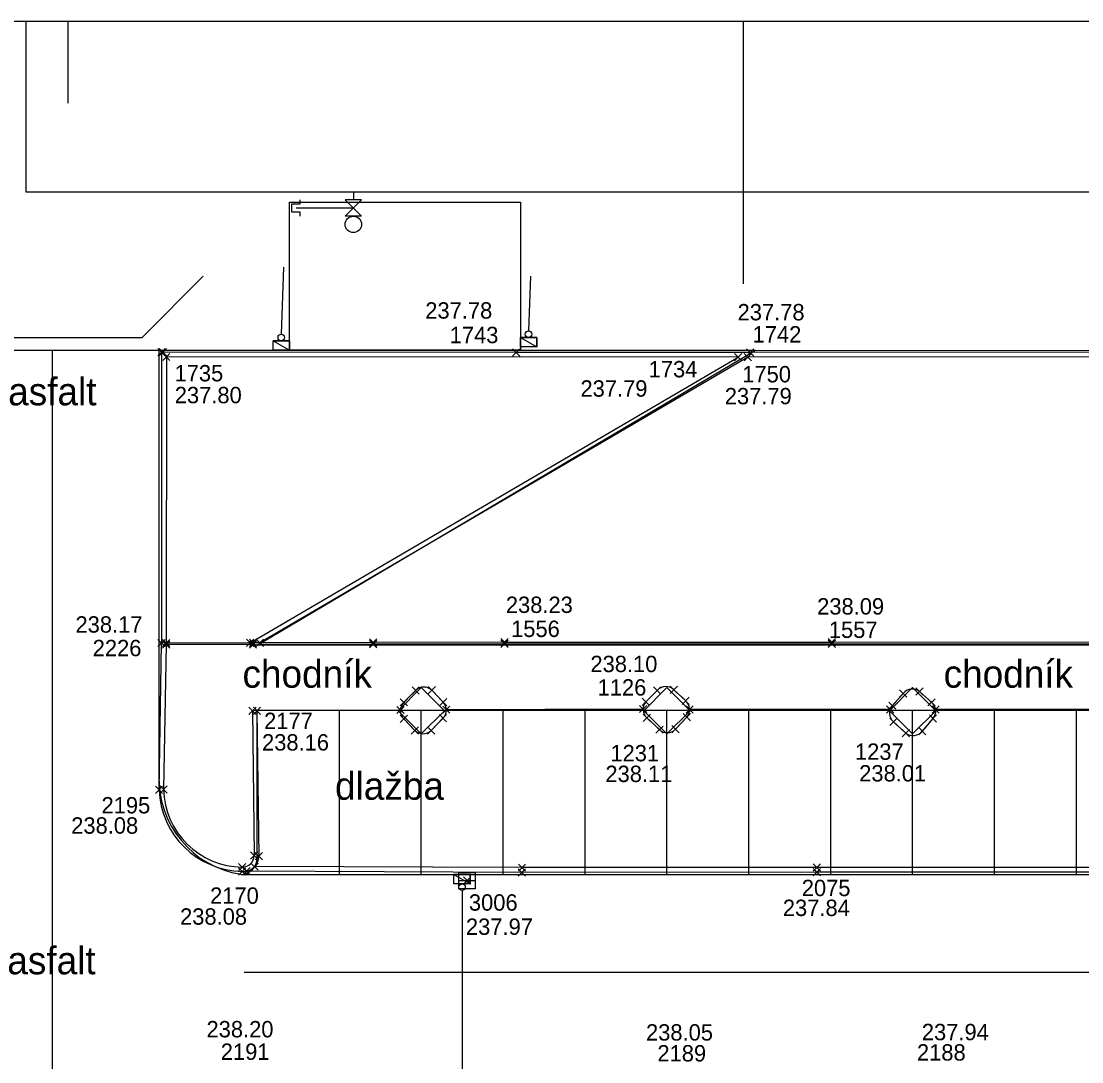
# Model space of a CAD drawing. Extents: x -264165 to -263733, y -1242319 to -1242245.
# Drawn here: x -263924.28 to -263891.9, y -1242276.71 to -1242244.94 of the extents above; entities that cross this region are included whole.
import ezdxf

# ---------------------------------------------------------------- set-up
doc = ezdxf.new("R2010")
doc.units = 0
for name, color, linetype in [('KFA_BOD_CISLO', 7, 'Continuous'), ('KFA_BOD_SYMBOL', 7, 'Continuous'), ('KFA_BOD_VYSKA', 7, 'Continuous'), ('KFA_SO_20-2_OBRUBNIKY_DOLNA_HRANA', 7, 'Continuous'), ('KFA_SO_20-2_OBRUBNIKY_HORNA_HRANA', 7, 'Continuous'), ('KFA_UV_BOD_CISLO', 7, 'Continuous'), ('KFA_UV_BOD_SYMBOL', 7, 'Continuous'), ('KFA_UV_BOD_VYSKA', 7, 'Continuous'), ('POPIS', 7, 'Continuous'), ('PROJEKT_OBRUBNIKY_KOMUNIKACIE', 7, 'Continuous'), ('PROJEKT_TDZ_VODOROVNE', 7, 'Continuous'), ('RAM_NA_TLAC_1-250', 7, 'Continuous'), ('SITUACIA_DSP_2D', 7, 'Continuous'), ('ULICNA_VPUST_POKLOP', 7, 'Continuous')]:
    doc.layers.add(name, color=color, linetype=linetype)

msp = doc.modelspace()

# ---------------------------------------------------------------- linework, layer by layer
at = {"layer": 'KFA_BOD_SYMBOL'}
for p, q in [((-263920.112, -1242255.15), (-263919.891, -1242254.93)), ((-263919.891, -1242255.15), (-263920.112, -1242254.93)), ((-263920.112, -1242255.15), (-263919.891, -1242254.93)), ((-263919.891, -1242255.15), (-263920.112, -1242254.93)), ((-263920.067, -1242255.15), (-263919.845, -1242254.93)), ((-263919.845, -1242255.15), (-263920.067, -1242254.93)), ((-263909.285, -1242255.159), (-263909.064, -1242254.938)), ((-263909.064, -1242255.159), (-263909.285, -1242254.938)), ((-263902.139, -1242255.157), (-263901.918, -1242254.937)), ((-263901.918, -1242255.157), (-263902.139, -1242254.937)), ((-263919.963, -1242255.298), (-263919.742, -1242255.076)), ((-263919.742, -1242255.298), (-263919.963, -1242255.076)), ((-263902.502, -1242255.303), (-263902.28, -1242255.083)), ((-263902.28, -1242255.303), (-263902.502, -1242255.083)), ((-263902.208, -1242255.302), (-263901.986, -1242255.08)), ((-263901.986, -1242255.302), (-263902.208, -1242255.08)), ((-263913.649, -1242264.015), (-263913.427, -1242263.795)), ((-263913.427, -1242264.015), (-263913.649, -1242263.795)), ((-263909.638, -1242264.008), (-263909.416, -1242263.786)), ((-263909.416, -1242264.008), (-263909.638, -1242263.786)), ((-263899.648, -1242264.005), (-263899.427, -1242263.785)), ((-263899.427, -1242264.005), (-263899.648, -1242263.785)), ((-263920.111, -1242264.031), (-263919.889, -1242263.809)), ((-263919.889, -1242264.031), (-263920.111, -1242263.809)), ((-263919.967, -1242264.031), (-263919.746, -1242263.809)), ((-263919.746, -1242264.031), (-263919.967, -1242263.809)), ((-263919.967, -1242264.08), (-263919.746, -1242263.86)), ((-263919.746, -1242264.08), (-263919.967, -1242263.86)), ((-263917.405, -1242264.026), (-263917.183, -1242263.806)), ((-263917.183, -1242264.026), (-263917.405, -1242263.806)), ((-263917.317, -1242264.026), (-263917.095, -1242263.806)), ((-263917.095, -1242264.026), (-263917.317, -1242263.806)), ((-263917.317, -1242264.076), (-263917.095, -1242263.856)), ((-263917.095, -1242264.076), (-263917.317, -1242263.856)), ((-263917.106, -1242264.025), (-263916.884, -1242263.805)), ((-263916.884, -1242264.025), (-263917.106, -1242263.805)), ((-263913.649, -1242264.066), (-263913.427, -1242263.845)), ((-263913.427, -1242264.066), (-263913.649, -1242263.845)), ((-263909.638, -1242264.058), (-263909.416, -1242263.836)), ((-263909.416, -1242264.058), (-263909.638, -1242263.836)), ((-263899.648, -1242264.056), (-263899.427, -1242263.835)), ((-263899.427, -1242264.056), (-263899.648, -1242263.835)), ((-263912.351, -1242265.477), (-263912.13, -1242265.255)), ((-263912.13, -1242265.477), (-263912.351, -1242265.255)), ((-263911.861, -1242265.471), (-263911.639, -1242265.251)), ((-263911.639, -1242265.471), (-263911.861, -1242265.251)), ((-263904.976, -1242265.482), (-263904.755, -1242265.262)), ((-263904.755, -1242265.482), (-263904.976, -1242265.262)), ((-263904.47, -1242265.458), (-263904.25, -1242265.237)), ((-263904.25, -1242265.458), (-263904.47, -1242265.237)), ((-263897.47, -1242265.57), (-263897.248, -1242265.35)), ((-263897.248, -1242265.57), (-263897.47, -1242265.35)), ((-263896.97, -1242265.512), (-263896.748, -1242265.292)), ((-263896.748, -1242265.512), (-263896.97, -1242265.292)), ((-263912.709, -1242265.84), (-263912.487, -1242265.62)), ((-263912.487, -1242265.84), (-263912.709, -1242265.62)), ((-263911.513, -1242265.836), (-263911.291, -1242265.615)), ((-263911.291, -1242265.836), (-263911.513, -1242265.615)), ((-263905.323, -1242265.826), (-263905.101, -1242265.606)), ((-263905.101, -1242265.826), (-263905.323, -1242265.606)), ((-263904.107, -1242265.792), (-263903.886, -1242265.572)), ((-263903.886, -1242265.792), (-263904.107, -1242265.572)), ((-263897.799, -1242265.944), (-263897.578, -1242265.722)), ((-263897.578, -1242265.944), (-263897.799, -1242265.722)), ((-263896.601, -1242265.84), (-263896.379, -1242265.62)), ((-263896.379, -1242265.84), (-263896.601, -1242265.62)), ((-263917.333, -1242266.102), (-263917.111, -1242265.88)), ((-263917.111, -1242266.102), (-263917.333, -1242265.88)), ((-263917.196, -1242266.102), (-263916.975, -1242265.88)), ((-263916.975, -1242266.102), (-263917.196, -1242265.88)), ((-263912.817, -1242266.076), (-263912.595, -1242265.856)), ((-263912.595, -1242266.076), (-263912.817, -1242265.856)), ((-263911.415, -1242266.066), (-263911.193, -1242265.846)), ((-263911.193, -1242266.066), (-263911.415, -1242265.846)), ((-263905.406, -1242266.046), (-263905.185, -1242265.825)), ((-263905.185, -1242266.046), (-263905.406, -1242265.825)), ((-263903.985, -1242266.062), (-263903.764, -1242265.842)), ((-263903.764, -1242266.062), (-263903.985, -1242265.842)), ((-263897.866, -1242266.062), (-263897.644, -1242265.842)), ((-263897.644, -1242266.062), (-263897.866, -1242265.842)), ((-263896.476, -1242266.059), (-263896.255, -1242265.838)), ((-263896.255, -1242266.059), (-263896.476, -1242265.838)), ((-263912.714, -1242266.345), (-263912.492, -1242266.123)), ((-263912.492, -1242266.345), (-263912.714, -1242266.123)), ((-263911.517, -1242266.329), (-263911.296, -1242266.107)), ((-263911.296, -1242266.329), (-263911.517, -1242266.107)), ((-263905.294, -1242266.319), (-263905.073, -1242266.097)), ((-263905.073, -1242266.319), (-263905.294, -1242266.097)), ((-263904.073, -1242266.298), (-263903.852, -1242266.076)), ((-263903.852, -1242266.298), (-263904.073, -1242266.076)), ((-263897.764, -1242266.437), (-263897.543, -1242266.215)), ((-263897.543, -1242266.437), (-263897.764, -1242266.215)), ((-263896.558, -1242266.339), (-263896.337, -1242266.117)), ((-263896.337, -1242266.339), (-263896.558, -1242266.117)), ((-263912.377, -1242266.698), (-263912.155, -1242266.477)), ((-263912.155, -1242266.698), (-263912.377, -1242266.477)), ((-263911.879, -1242266.698), (-263911.658, -1242266.478)), ((-263911.658, -1242266.698), (-263911.879, -1242266.478)), ((-263904.909, -1242266.676), (-263904.688, -1242266.454)), ((-263904.688, -1242266.676), (-263904.909, -1242266.454)), ((-263904.42, -1242266.664), (-263904.198, -1242266.443)), ((-263904.198, -1242266.664), (-263904.42, -1242266.443)), ((-263897.384, -1242266.782), (-263897.163, -1242266.562)), ((-263897.163, -1242266.782), (-263897.384, -1242266.562)), ((-263896.883, -1242266.718), (-263896.662, -1242266.497)), ((-263896.662, -1242266.718), (-263896.883, -1242266.497)), ((-263920.187, -1242268.512), (-263919.965, -1242268.291)), ((-263919.965, -1242268.512), (-263920.187, -1242268.291)), ((-263920.045, -1242268.501), (-263919.823, -1242268.279)), ((-263919.823, -1242268.501), (-263920.045, -1242268.279)), ((-263917.285, -1242270.519), (-263917.063, -1242270.298)), ((-263917.063, -1242270.519), (-263917.285, -1242270.298)), ((-263917.137, -1242270.536), (-263916.916, -1242270.316)), ((-263916.916, -1242270.536), (-263917.137, -1242270.316)), ((-263917.649, -1242271.007), (-263917.428, -1242270.785)), ((-263917.428, -1242271.007), (-263917.649, -1242270.785)), ((-263917.647, -1242270.872), (-263917.426, -1242270.65)), ((-263917.426, -1242270.872), (-263917.647, -1242270.65)), ((-263917.511, -1242270.995), (-263917.29, -1242270.775)), ((-263917.29, -1242270.995), (-263917.511, -1242270.775)), ((-263917.269, -1242270.857), (-263917.047, -1242270.637)), ((-263917.047, -1242270.857), (-263917.269, -1242270.637)), ((-263909.107, -1242271.034), (-263908.886, -1242270.812)), ((-263908.886, -1242271.034), (-263909.107, -1242270.812)), ((-263909.104, -1242270.889), (-263908.883, -1242270.667)), ((-263908.883, -1242270.889), (-263909.104, -1242270.667)), ((-263900.106, -1242271.029), (-263899.884, -1242270.809)), ((-263899.884, -1242271.029), (-263900.106, -1242270.809)), ((-263900.1, -1242270.887), (-263899.878, -1242270.666)), ((-263899.878, -1242270.887), (-263900.1, -1242270.666))]:
    msp.add_line(p, q, dxfattribs=at)
at = {"layer": 'KFA_SO_20-2_OBRUBNIKY_DOLNA_HRANA'}
for p in [(-263920.002, -1242255.04), (-263920.076, -1242268.401)]:
    msp.add_line(p, (-263920, -1242263.92), dxfattribs=at)
for points in [[(-263917.085, -1242265.991), (-263917.026, -1242270.426)], [(-263870.27, -1242270.923), (-263879.971, -1242270.913), (-263889.978, -1242270.919), (-263899.995, -1242270.919), (-263908.997, -1242270.923), (-263917.4, -1242270.885)], [(-263870.268, -1242270.778), (-263879.968, -1242270.77), (-263889.973, -1242270.776), (-263899.989, -1242270.776), (-263908.993, -1242270.778), (-263917.158, -1242270.747)]]:
    msp.add_lwpolyline(points, dxfattribs=at)
for centre, major_axis, ratio, start_param, end_param in [((-263917.484, -1242268.303), (-1.968, 1.69), 0.999578, 0.747286, 2.258757), ((-263917.505, -1242270.418), (0.358, 0.32), 0.994399, 3.915611, 5.536365)]:
    msp.add_ellipse(centre, major_axis=major_axis, ratio=ratio, start_param=start_param, end_param=end_param, dxfattribs=at)
at = {"layer": 'KFA_SO_20-2_OBRUBNIKY_HORNA_HRANA'}
for p, q in [((-263919.856, -1242263.97), (-263919.934, -1242268.39)), ((-263912.241, -1242265.366), (-263912.598, -1242265.73)), ((-263911.75, -1242265.361), (-263911.402, -1242265.725)), ((-263905.212, -1242265.716), (-263904.866, -1242265.372)), ((-263904.36, -1242265.347), (-263903.997, -1242265.682)), ((-263896.859, -1242265.402), (-263896.49, -1242265.73)), ((-263897.688, -1242265.833), (-263897.359, -1242265.46)), ((-263912.706, -1242265.966), (-263917.222, -1242265.991)), ((-263905.296, -1242265.935), (-263911.304, -1242265.956)), ((-263897.755, -1242265.952), (-263903.874, -1242265.952)), ((-263890.301, -1242265.948), (-263896.366, -1242265.948)), ((-263912.603, -1242266.234), (-263912.266, -1242266.587)), ((-263911.406, -1242266.218), (-263911.769, -1242266.588)), ((-263905.183, -1242266.208), (-263904.798, -1242266.565)), ((-263903.963, -1242266.187), (-263904.309, -1242266.553)), ((-263897.654, -1242266.326), (-263897.274, -1242266.672)), ((-263896.448, -1242266.228), (-263896.773, -1242266.607))]:
    msp.add_line(p, q, dxfattribs=at)
for points in [[(-263854.465, -1242263.815), (-263854.458, -1242255.02), (-263866.883, -1242255.042), (-263883.752, -1242255.044), (-263902.029, -1242255.047), (-263909.175, -1242255.048), (-263919.956, -1242255.04), (-263920.002, -1242255.04)], [(-263917.294, -1242263.916), (-263902.391, -1242255.193), (-263919.852, -1242255.187), (-263919.856, -1242263.92)], [(-263854.511, -1242263.815), (-263854.507, -1242255.162), (-263866.835, -1242255.182), (-263883.768, -1242255.184), (-263902.097, -1242255.191), (-263916.995, -1242263.915)], [(-263909.527, -1242263.897), (-263899.537, -1242263.895), (-263889.544, -1242263.882), (-263879.556, -1242263.864), (-263869.563, -1242263.857), (-263859.593, -1242263.827), (-263846.594, -1242263.797), (-263839.607, -1242263.784)], [(-263909.527, -1242263.897), (-263913.538, -1242263.905), (-263917.206, -1242263.916), (-263919.856, -1242263.92)], [(-263909.527, -1242263.947), (-263913.538, -1242263.955), (-263917.206, -1242263.966), (-263919.856, -1242263.97)], [(-263909.527, -1242263.947), (-263899.537, -1242263.945), (-263889.544, -1242263.932), (-263879.556, -1242263.914), (-263869.563, -1242263.907), (-263859.593, -1242263.877), (-263846.594, -1242263.847), (-263839.607, -1242263.834)], [(-263917.222, -1242265.991), (-263917.174, -1242270.408)]]:
    msp.add_lwpolyline(points, dxfattribs=at)
msp.add_arc((-263912.017, -1242266.348), 0.345, 223.8416, 315.9279, dxfattribs=at)
for centre, major_axis, ratio, start_param, end_param in [((-263911.993, -1242265.619), (-0.341, -0.097), 0.99952, 3.681968, 5.210546), ((-263904.601, -1242265.594), (-0.248, -0.24), 0.999714, 3.168237, 4.815804), ((-263897.08, -1242265.677), (-0.337, 0.105), 0.999988, 4.336062, 5.921787), ((-263912.353, -1242265.984), (-0.305, -0.179), 0.999732, 4.947712, 6.534947), ((-263911.657, -1242265.969), (0.051, 0.35), 0.999888, 4.076419, 5.61978), ((-263904.94, -1242265.947), (0.178, -0.31), 0.999907, 3.488193, 5.012441), ((-263904.231, -1242265.951), (-0.086, 0.346), 0.999744, 3.748769, 5.325059), ((-263896.711, -1242265.999), (0.173, 0.303), 0.999776, 4.516854, 6.114702), ((-263897.418, -1242266.062), (0.194, -0.296), 0.999691, 3.429132, 4.975104), ((-263904.56, -1242266.313), (0.029, 0.346), 0.999966, 2.4673, 4.032869), ((-263897.056, -1242266.392), (0.079, -0.346), 0.99984, 5.398046, 6.980374), ((-263917.51, -1242268.336), (1.808, -1.616), 0.999931, 3.892932, 5.430703), ((-263917.53, -1242270.405), (0.102, 0.341), 0.998375, 3.415738, 4.994729)]:
    msp.add_ellipse(centre, major_axis=major_axis, ratio=ratio, start_param=start_param, end_param=end_param, dxfattribs=at)
at = {"layer": 'KFA_UV_BOD_SYMBOL'}
for p, q in [((-263910.78, -1242271.284), (-263910.558, -1242271.062)), ((-263910.558, -1242271.284), (-263910.78, -1242271.062))]:
    msp.add_line(p, q, dxfattribs=at)
at = {"layer": 'PROJEKT_OBRUBNIKY_KOMUNIKACIE'}
for p, q in [((-263916.093, -1242254.982), (-263916.093, -1242250.458)), ((-263916.093, -1242250.458), (-263909.043, -1242250.458)), ((-263909.043, -1242250.458), (-263909.043, -1242254.982)), ((-263929.58, -1242254.982), (-263920.08, -1242254.982)), ((-263920.08, -1242254.982), (-263920.08, -1242267.983)), ((-263920.08, -1242254.982), (-263901.868, -1242254.982)), ((-263909.043, -1242254.982), (-263916.093, -1242254.982)), ((-263807.068, -1242265.987), (-263917.08, -1242265.983)), ((-263917.08, -1242270.483), (-263917.08, -1242265.983)), ((-263917.578, -1242270.983), (-263807.068, -1242270.982))]:
    msp.add_line(p, q, dxfattribs=at)
for points in [[(-263854.468, -1242263.985), (-263917.08, -1242263.982), (-263901.868, -1242254.982), (-263854.468, -1242254.985), (-263854.468, -1242263.985)], [(-263912.068, -1242265.279), (-263911.361, -1242265.986), (-263912.068, -1242266.694), (-263912.775, -1242265.986), (-263912.068, -1242265.279)], [(-263904.568, -1242265.279), (-263903.861, -1242265.986), (-263904.568, -1242266.694), (-263905.275, -1242265.986), (-263904.568, -1242265.279)], [(-263897.068, -1242265.279), (-263896.361, -1242265.986), (-263897.068, -1242266.694), (-263897.775, -1242265.986), (-263897.068, -1242265.279)], [(-263897.068, -1242265.279), (-263896.361, -1242265.986), (-263897.068, -1242266.694), (-263897.775, -1242265.986), (-263897.068, -1242265.279)]]:
    msp.add_lwpolyline(points, dxfattribs=at)
for centre, radius, start, end in [((-263917.122, -1242268.058), 2.959, 178.5315, 261.1367), ((-263917.58, -1242270.483), 0.5, 270.2865, 0)]:
    msp.add_arc(centre, radius, start, end, dxfattribs=at)
at = {"layer": 'PROJEKT_TDZ_VODOROVNE'}
for p, q in [((-263923.33, -1242296.482), (-263923.33, -1242254.982)), ((-263914.568, -1242270.982), (-263914.568, -1242265.982)), ((-263912.068, -1242270.982), (-263912.068, -1242265.982)), ((-263909.568, -1242270.982), (-263909.568, -1242265.982)), ((-263907.068, -1242270.982), (-263907.068, -1242265.982)), ((-263904.568, -1242270.982), (-263904.568, -1242265.982)), ((-263902.068, -1242270.982), (-263902.068, -1242265.982)), ((-263899.568, -1242270.982), (-263899.568, -1242265.982)), ((-263897.068, -1242270.982), (-263897.068, -1242265.982)), ((-263894.568, -1242270.982), (-263894.568, -1242265.982)), ((-263892.068, -1242270.982), (-263892.068, -1242265.982)), ((-263817.068, -1242273.982), (-263917.477, -1242273.982))]:
    msp.add_line(p, q, dxfattribs=at)
at = {"layer": 'RAM_NA_TLAC_1-250'}
msp.add_line((-263922.863, -1242244.935), (-263922.863, -1242247.435), dxfattribs=at)
msp.add_lwpolyline([(-264165.363, -1242244.935), (-263732.863, -1242244.935), (-263732.863, -1242319.185), (-264165.363, -1242319.185)], close=True, dxfattribs=at)
at = {"layer": 'SITUACIA_DSP_2D'}
for p, q in [((-263924.143, -1242244.935), (-263924.143, -1242250.14)), ((-263902.238, -1242244.935), (-263902.238, -1242252.949)), ((-263924.143, -1242250.14), (-263788.143, -1242250.14)), ((-263914.143, -1242250.14), (-263914.143, -1242250.39)), ((-263914.143, -1242250.14), (-263914.143, -1242250.39)), ((-263916.093, -1242254.982), (-263916.093, -1242250.458)), ((-263916.093, -1242250.458), (-263909.043, -1242250.458)), ((-263916.018, -1242250.515), (-263915.768, -1242250.515)), ((-263916.018, -1242250.765), (-263916.018, -1242250.515)), ((-263915.768, -1242250.515), (-263915.768, -1242250.39)), ((-263914.393, -1242250.39), (-263913.893, -1242250.89)), ((-263913.893, -1242250.39), (-263914.393, -1242250.39)), ((-263914.393, -1242250.89), (-263913.893, -1242250.39)), ((-263909.043, -1242250.458), (-263909.043, -1242254.982)), ((-263915.768, -1242250.765), (-263916.018, -1242250.765)), ((-263914.143, -1242250.64), (-263915.893, -1242250.64)), ((-263915.768, -1242250.89), (-263915.768, -1242250.765)), ((-263913.893, -1242250.89), (-263914.393, -1242250.89)), ((-263916.339, -1242254.492), (-263916.265, -1242252.443)), ((-263920.595, -1242254.592), (-263918.723, -1242252.72)), ((-263908.789, -1242254.387), (-263908.729, -1242252.715)), ((-263929.73, -1242254.592), (-263920.595, -1242254.592)), ((-263916.593, -1242254.692), (-263916.093, -1242254.692)), ((-263916.593, -1242254.982), (-263916.593, -1242254.692)), ((-263916.593, -1242254.692), (-263916.093, -1242254.982)), ((-263916.593, -1242254.692), (-263916.093, -1242254.982)), ((-263916.093, -1242254.692), (-263916.593, -1242254.692)), ((-263916.093, -1242254.692), (-263916.093, -1242254.982)), ((-263916.093, -1242254.982), (-263916.093, -1242254.692)), ((-263909.043, -1242254.587), (-263908.543, -1242254.587)), ((-263909.043, -1242254.877), (-263909.043, -1242254.587)), ((-263909.043, -1242254.587), (-263908.543, -1242254.877)), ((-263909.043, -1242254.587), (-263908.543, -1242254.877)), ((-263908.543, -1242254.587), (-263909.043, -1242254.587)), ((-263908.543, -1242254.587), (-263908.543, -1242254.877)), ((-263908.543, -1242254.877), (-263908.543, -1242254.587)), ((-263916.093, -1242254.982), (-263916.593, -1242254.982)), ((-263909.043, -1242254.982), (-263916.093, -1242254.982)), ((-263908.543, -1242254.877), (-263909.043, -1242254.877)), ((-263911.074, -1242270.983), (-263910.574, -1242270.983)), ((-263911.074, -1242271.273), (-263911.074, -1242270.983)), ((-263911.074, -1242270.983), (-263910.574, -1242271.273)), ((-263911.074, -1242270.983), (-263910.574, -1242271.273)), ((-263910.574, -1242270.983), (-263911.074, -1242270.983)), ((-263910.574, -1242270.983), (-263910.574, -1242271.273)), ((-263910.574, -1242271.273), (-263910.574, -1242270.983)), ((-263910.574, -1242271.273), (-263911.074, -1242271.273)), ((-263910.824, -1242271.473), (-263910.824, -1242283.187))]:
    msp.add_line(p, q, dxfattribs=at)
msp.add_lwpolyline([(-263854.468, -1242263.985), (-263917.08, -1242263.982), (-263901.868, -1242254.982), (-263854.468, -1242254.985), (-263854.468, -1242263.985)], dxfattribs=at)
for points in [[(-263912.068, -1242265.279), (-263911.361, -1242265.986), (-263912.068, -1242266.693), (-263912.775, -1242265.986)], [(-263904.568, -1242265.279), (-263903.861, -1242265.986), (-263904.568, -1242266.693), (-263905.275, -1242265.986)], [(-263897.068, -1242265.279), (-263896.361, -1242265.986), (-263897.068, -1242266.693), (-263897.775, -1242265.986)], [(-263897.068, -1242265.279), (-263896.361, -1242265.986), (-263897.068, -1242266.693), (-263897.775, -1242265.986)]]:
    msp.add_lwpolyline(points, close=True, dxfattribs=at)
for centre, radius in [((-263914.143, -1242251.14), 0.25), ((-263908.793, -1242254.487), 0.1), ((-263916.343, -1242254.592), 0.1), ((-263910.824, -1242271.373), 0.1)]:
    msp.add_circle(centre, radius, dxfattribs=at)
at = {"layer": 'ULICNA_VPUST_POKLOP'}
msp.add_line((-263910.669, -1242271.173), (-263910.669, -1242271.173), dxfattribs=at)
msp.add_lwpolyline([(-263910.919, -1242271.173), (-263910.919, -1242270.923), (-263910.419, -1242270.923), (-263910.419, -1242271.423), (-263910.919, -1242271.423), (-263910.919, -1242271.173), (-263910.419, -1242271.173)], dxfattribs=at)

# ---------------------------------------------------------------- texts
at = {"layer": 'KFA_BOD_CISLO'}
for s, p in [('1743', (-263911.202, -1242254.765)), ('1742', (-263901.954, -1242254.745)), ('1734', (-263905.127, -1242255.809)), ('1735', (-263919.602, -1242255.932)), ('1750', (-263902.269, -1242255.962)), ('1556', (-263909.327, -1242263.736)), ('1557', (-263899.626, -1242263.765)), ('2226', (-263922.1, -1242264.323)), ('1126', (-263906.686, -1242265.525)), ('2177', (-263916.868, -1242266.547)), ('1231', (-263906.295, -1242267.532)), ('1237', (-263898.829, -1242267.486)), ('2195', (-263921.831, -1242269.123)), ('2075', (-263900.452, -1242271.648)), ('2170', (-263918.517, -1242271.881)), ('2191', (-263918.19, -1242276.647)), ('2189', (-263904.86, -1242276.696)), ('2188', (-263896.936, -1242276.669))]:
    msp.add_text(s, height=0.5, dxfattribs=at).set_placement(p)
at = {"layer": 'KFA_BOD_VYSKA'}
for s, p in [('237.78', (-263911.947, -1242254.016)), ('237.78', (-263902.412, -1242254.069)), ('237.79', (-263907.209, -1242256.399)), ('237.80', (-263919.595, -1242256.599)), ('237.79', (-263902.803, -1242256.631)), ('238.23', (-263909.487, -1242263.002)), ('238.09', (-263899.983, -1242263.05)), ('238.17', (-263922.626, -1242263.603)), ('238.10', (-263906.905, -1242264.808)), ('238.16', (-263916.931, -1242267.203)), ('238.11', (-263906.448, -1242268.164)), ('238.01', (-263898.7, -1242268.147)), ('238.08', (-263922.756, -1242269.741)), ('237.84', (-263901.03, -1242272.255)), ('238.08', (-263919.433, -1242272.52)), ('238.20', (-263918.626, -1242275.96)), ('238.05', (-263905.208, -1242276.058)), ('237.94', (-263896.787, -1242276.047))]:
    msp.add_text(s, height=0.5, dxfattribs=at).set_placement(p)
at = {"layer": 'KFA_UV_BOD_CISLO'}
msp.add_text('3006', height=0.5, dxfattribs=at).set_placement((-263910.615, -1242272.092))
at = {"layer": 'KFA_UV_BOD_VYSKA'}
msp.add_text('237.97', height=0.5, dxfattribs=at).set_placement((-263910.705, -1242272.83))
at = {"layer": 'POPIS'}
for s, p in [('asfalt', (-263924.681, -1242256.663)), ('chodník', (-263917.527, -1242265.285)), ('chodník', (-263896.122, -1242265.285)), ('dlažba', (-263914.702, -1242268.705)), ('asfalt', (-263924.707, -1242274.034))]:
    msp.add_text(s, height=0.8438, dxfattribs=at).set_placement(p)

doc.saveas('drawing.dxf')
